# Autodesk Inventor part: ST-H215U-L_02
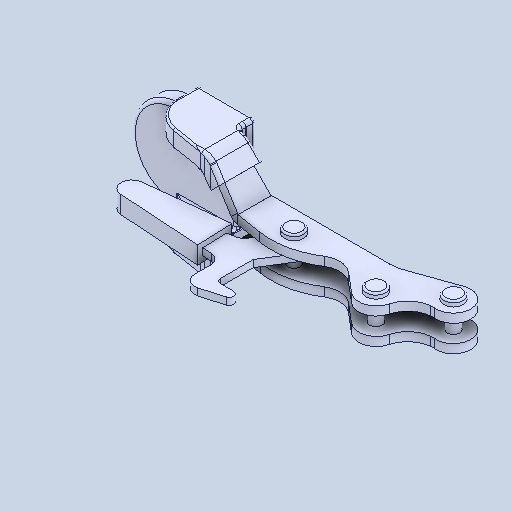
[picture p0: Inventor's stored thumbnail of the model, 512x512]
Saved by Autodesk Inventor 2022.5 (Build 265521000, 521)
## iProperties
Created: 2024-07
Part Number: ST-H215U-L_02
Material: 一般
Document SubType Name: Modeling
Designer: ImaoCorp
Density: 1 g/cm^3
Appearance: 既定
Author: ImaoCorp
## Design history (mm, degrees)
feature "ST-H215U-L_02"
node "ソリッド1"
